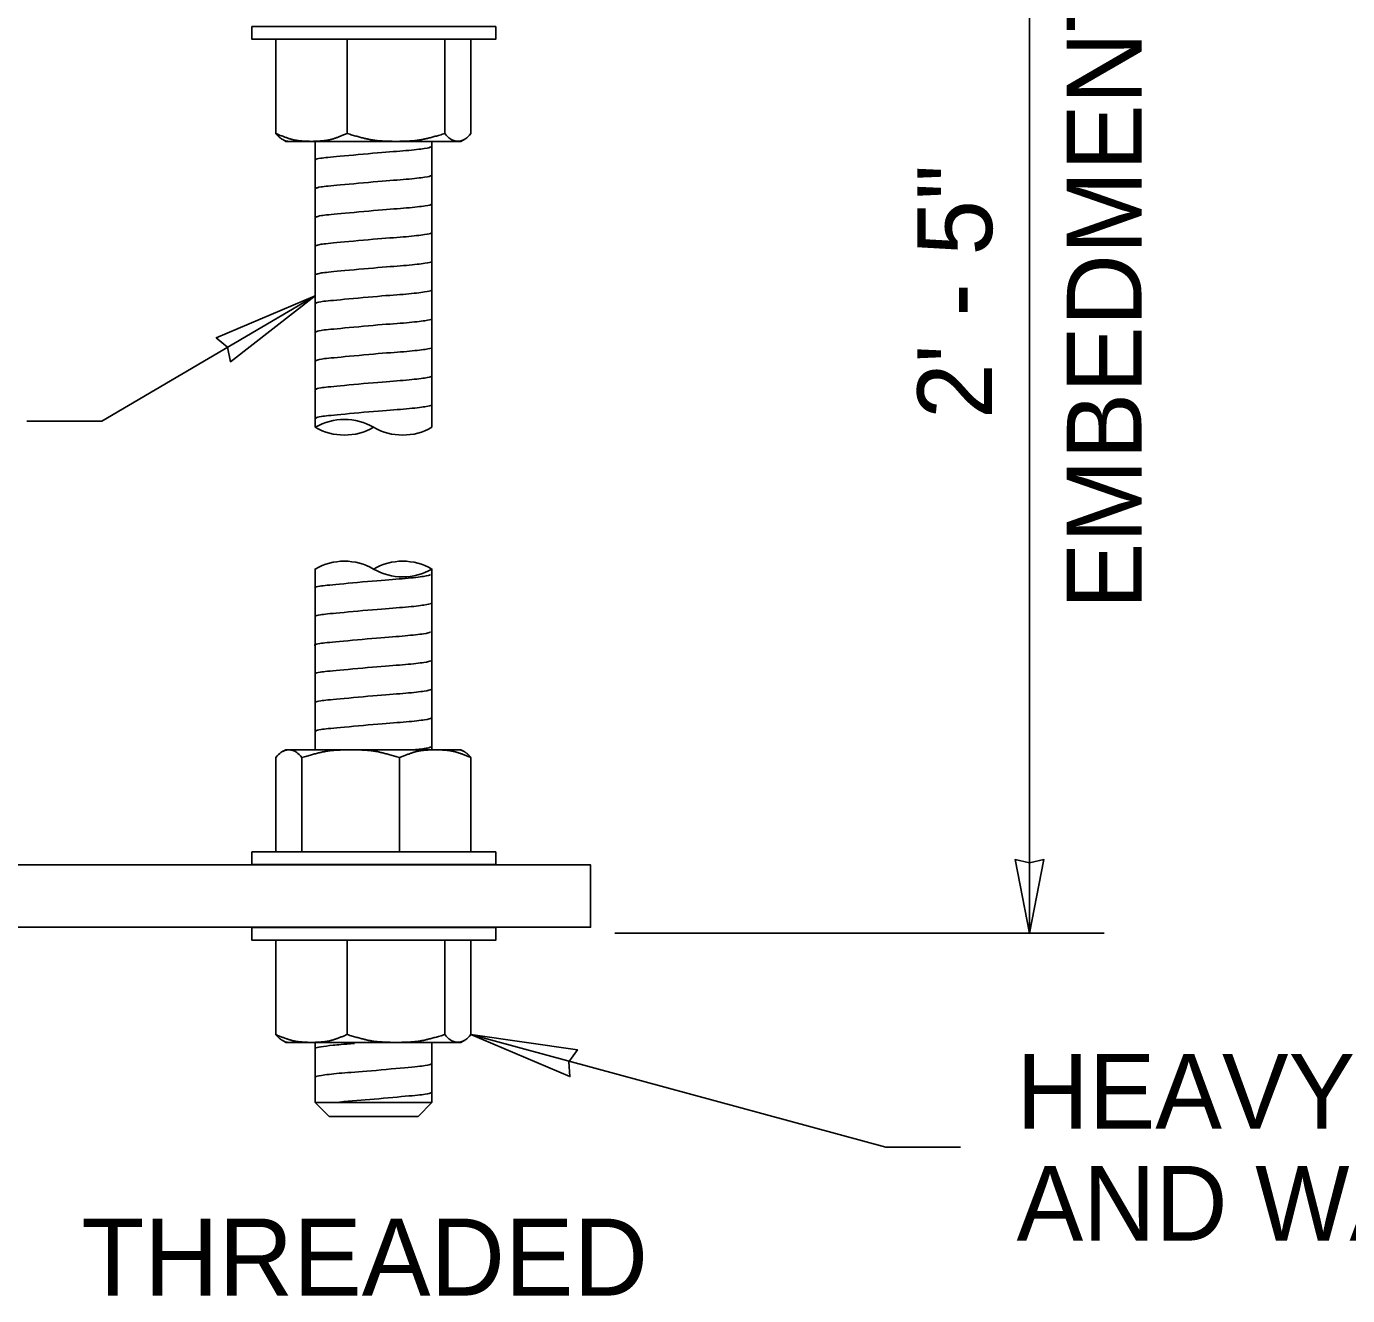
# Model space of a CAD drawing. Extents: x 99862 to 103680, y 99594 to 102199.
# Drawn here: x 101383.8 to 101666.8, y 100646 to 100917.9 of the extents above; entities that cross this region are included whole.
import ezdxf

# ---------------------------------------------------------------- set-up
doc = ezdxf.new("R2010")
doc.units = 0
for name, color, linetype in [('Level 15', 7, 'Continuous'), ('Level 19', 7, 'Continuous'), ('Level 20', 7, 'Continuous'), ('Level 9', 7, 'Continuous')]:
    doc.layers.add(name, color=color, linetype=linetype)

msp = doc.modelspace()

# ---------------------------------------------------------------- linework, layer by layer
at = {"layer": 'Level 15'}
for p, q in [((101598.68, 100723.67), (101598.68, 101021.14)), ((101445.68, 100860.15), (101399.93, 100833.33)), ((101399.93, 100833.33), (101383.93, 100833.33)), ((101509.88, 100723.67), (101614.68, 100723.67)), ((101567.92, 100677.78), (101479.04, 100701.91)), ((101567.92, 100677.78), (101583.92, 100677.78))]:
    msp.add_line(p, q, dxfattribs=at)
for points in [[(101445.68, 100860.15), (101424.48, 100851.18), (101426.9, 100849.14), (101427.5, 100846.03)], [(101598.68, 100723.67), (101595.6, 100739.39), (101598.68, 100738.67), (101601.77, 100739.39)], [(101479.04, 100701.91), (101500.24, 100692.92), (101500.02, 100696.08), (101501.84, 100698.68)]]:
    msp.add_lwpolyline(points, close=True, dxfattribs=at)
at = {"layer": 'Level 19'}
msp.add_lwpolyline([(101318.38, 100738.26), (101504.66, 100738.26), (101504.66, 100724.9), (101318.38, 100724.9)], dxfattribs=at)
at = {"layer": 'Level 9'}
for p, q in [((101437.22, 100894.93), (101437.22, 100915.13)), ((101452.53, 100894.93), (101452.53, 100915.13)), ((101473.44, 100894.93), (101473.44, 100915.13)), ((101479.04, 100894.93), (101479.04, 100915.13)), ((101439.38, 100893.26), (101438.72, 100893.64)), ((101444.55, 100893.26), (101439.38, 100893.26)), ((101440.16, 100893.26), (101439.89, 100893.26)), ((101445.2, 100893.26), (101444.55, 100893.26)), ((101444.55, 100893.26), (101445.2, 100893.26)), ((101462.74, 100893.26), (101445.2, 100893.26)), ((101445.68, 100893.26), (101445.68, 100832.01)), ((101453.65, 100893.26), (101452.9, 100893.26)), ((101462.74, 100893.26), (101463.22, 100893.26)), ((101462.74, 100893.26), (101463.22, 100893.26)), ((101476.88, 100893.26), (101463.22, 100893.26)), ((101470.68, 100832.01), (101470.68, 100893.26)), ((101477.55, 100893.64), (101476.88, 100893.26)), ((101445.68, 100801.65), (101445.68, 100762.92)), ((101470.68, 100762.92), (101470.68, 100801.65)), ((101438.72, 100762.54), (101439.39, 100762.92)), ((101439.39, 100762.92), (101453.05, 100762.92)), ((101453.52, 100762.92), (101453.05, 100762.92)), ((101453.52, 100762.92), (101453.05, 100762.92)), ((101453.52, 100762.92), (101471.72, 100762.92)), ((101462.61, 100762.92), (101463.37, 100762.92)), ((101471.72, 100762.92), (101476.89, 100762.92)), ((101476.11, 100762.92), (101476.37, 100762.92)), ((101476.89, 100762.92), (101477.55, 100762.54)), ((101437.22, 100761.25), (101437.22, 100741.05)), ((101442.83, 100761.25), (101442.83, 100741.05)), ((101463.74, 100761.25), (101463.74, 100741.05)), ((101479.04, 100761.25), (101479.04, 100741.05)), ((101437.22, 100701.91), (101437.22, 100722.11)), ((101452.53, 100701.91), (101452.53, 100722.11)), ((101473.44, 100701.91), (101473.44, 100722.11)), ((101479.04, 100701.91), (101479.04, 100722.11)), ((101439.38, 100700.24), (101438.72, 100700.62)), ((101444.55, 100700.24), (101439.38, 100700.24)), ((101440.16, 100700.24), (101439.89, 100700.24)), ((101445.2, 100700.24), (101444.55, 100700.24)), ((101444.55, 100700.24), (101445.2, 100700.24)), ((101462.74, 100700.24), (101445.2, 100700.24)), ((101445.68, 100687.37), (101445.68, 100700.01)), ((101453.65, 100700.24), (101452.9, 100700.24)), ((101462.74, 100700.24), (101463.22, 100700.24)), ((101462.74, 100700.24), (101463.22, 100700.24)), ((101476.88, 100700.24), (101463.22, 100700.24)), ((101470.68, 100700.01), (101470.68, 100687.37)), ((101477.55, 100700.62), (101476.88, 100700.24)), ((101448.66, 100684.39), (101445.68, 100687.37)), ((101445.68, 100687.37), (101470.68, 100687.37)), ((101470.68, 100687.37), (101467.71, 100684.39)), ((101448.66, 100684.39), (101467.71, 100684.39))]:
    msp.add_line(p, q, dxfattribs=at)
for points in [[(101484.33, 100917.84), (101432.13, 100917.84), (101432.13, 100915.13), (101484.33, 100915.13)], [(101484.33, 100738.35), (101432.13, 100738.35), (101432.13, 100741.05), (101484.33, 100741.05)], [(101484.33, 100724.82), (101432.13, 100724.82), (101432.13, 100722.11), (101484.33, 100722.11)]]:
    msp.add_lwpolyline(points, close=True, dxfattribs=at)
for centre, start, end in [((101451.93, 100821.18), 60, 120), ((101451.93, 100842.83), 240, 300), ((101464.43, 100842.83), 240, 300), ((101451.93, 100790.82), 60, 120), ((101464.43, 100790.82), 60, 120), ((101464.43, 100812.47), 240, 300)]:
    msp.add_arc(centre, 12.5, start, end, dxfattribs=at)
for points, degree in [([(101438.75, 100893.62), (101438.24, 100893.91), (101437.73, 100894.37), (101437.22, 100894.93)], 2), ([(101437.22, 100894.93), (101439.61, 100893.95), (101442.07, 100893.31), (101444.55, 100893.26)], 2), ([(101439.89, 100893.26), (101439.51, 100893.28), (101439.13, 100893.41), (101438.75, 100893.62)], 2), ([(101445.2, 100893.26), (101447.69, 100893.31), (101450.16, 100893.96), (101452.53, 100894.93)], 2), ([(101452.53, 100894.93), (101455.87, 100893.93), (101459.26, 100893.28), (101462.74, 100893.26)], 2), ([(101463.22, 100893.26), (101466.69, 100893.28), (101470.1, 100893.93), (101473.44, 100894.93)], 2), ([(101473.44, 100894.93), (101474.35, 100893.91), (101475.28, 100893.26), (101477.19, 100893.26), (101478.13, 100893.91), (101479.04, 100894.93)], 3), ([(101445.63, 100889.27), (101445.64, 100889.29), (101445.67, 100889.3), (101446.37, 100889.65), (101450.06, 100889.97), (101459.63, 100890.88), (101465.35, 100891.25), (101469.55, 100891.77), (101470.32, 100891.92), (101470.51, 100892.11)], 3), ([(101445.7, 100883.13), (101445.72, 100883.14), (101445.74, 100883.16), (101446.45, 100883.5), (101450.14, 100883.83), (101459.71, 100884.74), (101465.43, 100885.1), (101469.62, 100885.63), (101470.4, 100885.78), (101470.59, 100885.96)], 3), ([(101445.78, 100876.99), (101445.8, 100877), (101445.82, 100877.01), (101446.53, 100877.36), (101450.22, 100877.69), (101459.79, 100878.6), (101465.5, 100878.96), (101469.7, 100879.48), (101470.48, 100879.64), (101470.66, 100879.82)], 3), ([(101445.68, 100870.84), (101445.69, 100870.85), (101445.72, 100870.86), (101446.42, 100871.21), (101450.11, 100871.54), (101459.68, 100872.45), (101465.4, 100872.81), (101469.59, 100873.33), (101470.37, 100873.49), (101470.56, 100873.67)], 3), ([(101445.75, 100864.69), (101445.77, 100864.71), (101445.79, 100864.72), (101446.5, 100865.07), (101450.19, 100865.39), (101459.76, 100866.3), (101465.48, 100866.67), (101469.67, 100867.19), (101470.45, 100867.34), (101470.64, 100867.53)], 3), ([(101445.65, 100858.54), (101445.66, 100858.55), (101445.69, 100858.57), (101446.39, 100858.91), (101450.08, 100859.24), (101459.65, 100860.15), (101465.37, 100860.51), (101469.57, 100861.04), (101470.34, 100861.19), (101470.53, 100861.37)], 3), ([(101445.72, 100852.4), (101445.74, 100852.41), (101445.76, 100852.42), (101446.47, 100852.77), (101450.16, 100853.1), (101459.73, 100854.01), (101465.45, 100854.37), (101469.64, 100854.89), (101470.42, 100855.05), (101470.61, 100855.23)], 3), ([(101445.8, 100846.26), (101445.82, 100846.27), (101445.84, 100846.28), (101446.55, 100846.63), (101450.24, 100846.96), (101459.81, 100847.87), (101465.52, 100848.23), (101469.72, 100848.75), (101470.5, 100848.91), (101470.68, 100849.09)], 3), ([(101445.7, 100840.1), (101445.71, 100840.12), (101445.74, 100840.13), (101446.44, 100840.48), (101450.13, 100840.8), (101459.7, 100841.72), (101465.42, 100842.08), (101469.61, 100842.6), (101470.39, 100842.75), (101470.58, 100842.94)], 3), ([(101445.77, 100833.96), (101445.79, 100833.97), (101445.81, 100833.99), (101446.52, 100834.33), (101450.21, 100834.66), (101459.78, 100835.57), (101465.5, 100835.93), (101469.69, 100836.46), (101470.47, 100836.61), (101470.66, 100836.79)], 3), ([(101445.49, 100797.62), (101445.5, 100797.63), (101445.53, 100797.64), (101446.23, 100797.99), (101449.92, 100798.32), (101459.49, 100799.23), (101465.21, 100799.59), (101469.4, 100800.11), (101470.18, 100800.27), (101470.37, 100800.45)], 3), ([(101445.56, 100791.48), (101445.58, 100791.49), (101445.6, 100791.5), (101446.31, 100791.85), (101450, 100792.18), (101459.57, 100793.09), (101465.29, 100793.45), (101469.48, 100793.97), (101470.26, 100794.13), (101470.45, 100794.31)], 3), ([(101445.46, 100785.32), (101445.48, 100785.34), (101445.5, 100785.35), (101446.2, 100785.7), (101449.89, 100786.02), (101459.46, 100786.93), (101465.18, 100787.3), (101469.38, 100787.82), (101470.15, 100787.97), (101470.34, 100788.16)], 3), ([(101445.53, 100779.18), (101445.55, 100779.19), (101445.57, 100779.21), (101446.28, 100779.55), (101449.97, 100779.88), (101459.54, 100780.79), (101465.26, 100781.15), (101469.45, 100781.68), (101470.23, 100781.83), (101470.42, 100782.01)], 3), ([(101445.61, 100773.04), (101445.63, 100773.05), (101445.65, 100773.06), (101446.36, 100773.41), (101450.05, 100773.74), (101459.62, 100774.65), (101465.34, 100775.01), (101469.53, 100775.53), (101470.31, 100775.69), (101470.49, 100775.87)], 3), ([(101445.69, 100766.9), (101445.71, 100766.91), (101445.73, 100766.92), (101446.44, 100767.27), (101450.13, 100767.6), (101459.7, 100768.51), (101465.41, 100768.87), (101469.61, 100769.39), (101470.39, 100769.55), (101470.57, 100769.73)], 3), ([(101442.83, 100761.25), (101441.91, 100762.27), (101440.98, 100762.92), (101439.08, 100762.93), (101438.14, 100762.27), (101437.22, 100761.25)], 3), ([(101453.05, 100762.92), (101449.57, 100762.9), (101446.16, 100762.25), (101442.83, 100761.25)], 2), ([(101463.74, 100761.25), (101460.39, 100762.25), (101457, 100762.9), (101453.52, 100762.92)], 2), ([(101471.06, 100762.92), (101468.58, 100762.87), (101466.11, 100762.22), (101463.74, 100761.25)], 2), ([(101466.83, 100762.92), (101467.33, 100762.97), (101467.78, 100763.02), (101469.5, 100763.24), (101470.28, 100763.39), (101470.47, 100763.58)], 3), ([(101479.04, 100761.25), (101476.66, 100762.23), (101474.19, 100762.87), (101471.72, 100762.92)], 2), ([(101476.37, 100762.92), (101476.76, 100762.9), (101477.14, 100762.77), (101477.51, 100762.56)], 2), ([(101477.51, 100762.56), (101478.03, 100762.27), (101478.54, 100761.82), (101479.04, 100761.25)], 2), ([(101438.75, 100700.6), (101438.24, 100700.89), (101437.73, 100701.35), (101437.22, 100701.91)], 2), ([(101437.22, 100701.91), (101439.61, 100700.93), (101442.07, 100700.29), (101444.55, 100700.24)], 2), ([(101439.89, 100700.24), (101439.51, 100700.26), (101439.13, 100700.39), (101438.75, 100700.6)], 2), ([(101445.2, 100700.24), (101447.69, 100700.29), (101450.16, 100700.94), (101452.53, 100701.91)], 2), ([(101454.1, 100700.01), (101451.61, 100699.81), (101449.39, 100699.63), (101446.65, 100699.28), (101445.93, 100699.12), (101445.7, 100698.9)], 3), ([(101452.53, 100701.91), (101455.87, 100700.91), (101459.26, 100700.26), (101462.74, 100700.24)], 2), ([(101463.22, 100700.24), (101466.69, 100700.26), (101470.1, 100700.91), (101473.44, 100701.91)], 2), ([(101473.44, 100701.91), (101474.35, 100700.89), (101475.28, 100700.24), (101477.19, 100700.24), (101478.13, 100700.89), (101479.04, 100701.91)], 3), ([(101470.7, 100695.71), (101470.66, 100695.67), (101470.6, 100695.63), (101469.75, 100695.26), (101465.75, 100694.91), (101456.04, 100693.98), (101450.53, 100693.64), (101446.57, 100693.13), (101445.82, 100692.97), (101445.7, 100692.77)], 3), ([(101470.7, 100689.57), (101470.66, 100689.53), (101470.6, 100689.49), (101469.75, 100689.12), (101465.75, 100688.77), (101457, 100687.94), (101452.58, 100687.63), (101449.85, 100687.37)], 3)]:
    msp.add_open_spline(points, degree=degree, dxfattribs=at)

# ---------------------------------------------------------------- texts
at = {"layer": 'Level 20'}
for s, p in [('EMBEDMENT', (101622.68, 100793.01)), ('2\' - 5"', (101590.68, 100833.8))]:
    msp.add_text(s, height=16, rotation=90, dxfattribs=at).set_placement(p)
for s, height, p in [('HEAVY HEX NUT', 16, (101595.92, 100681.78)), ('AND WASHER (TYP.)', 16, (101595.92, 100657.78)), ('THREADED', 16.5, (101395.59, 100646))]:
    msp.add_text(s, height=height, dxfattribs=at).set_placement(p)

doc.saveas('drawing.dxf')
